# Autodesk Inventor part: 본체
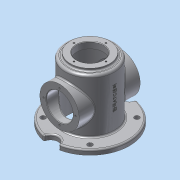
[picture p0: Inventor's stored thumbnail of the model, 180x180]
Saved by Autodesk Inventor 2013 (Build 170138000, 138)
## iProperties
Created: 2018-04
Part Number: 본체
Material: 알루미늄 6061
Document SubType Name: Modeling
Designer: dgall
Density: 2.71 g/cm^3
Mass: 1151.24 g
Surface Area: 1200.37 cm^2
Volume: 424.812 cm^3
Author: dgall
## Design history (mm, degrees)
sketch "스케치1"
  geometry: C1 r 50 at (0, 0); 1 further point
  constraints: 1 centre point, 1 coincident
  dimensions: "d0" = 100 diameter of C1
extrude "돌출1" new body sketch "스케치1" distance "d1" = 110; taper "d2" = 0 deg
fillet "모깎기1" dims "d3" = 5
sketch "스케치2"
  geometry: C1 r 45 at (0, 0) reference; C2 r 50 at (0, 0) reference; C3 r 80 at (0, 0)
  constraints: 1 centre point, 1 coincident
  dimensions: "d5" = 160 diameter of C3
extrude "돌출2" join sketch "스케치2" distance "d6" = 10; taper "d7" = 0 deg
sketch "스케치3"
  geometry: C1 r 45 at (0, 0) reference; C2 r 80 at (0, 0) reference; C3 r 50 at (0, 0)
  constraints: 1 centre point, 1 coincident
  dimensions: "d8" = 100 diameter of C3
extrude "돌출3" join sketch "스케치3" distance "d9" = 8; taper "d10" = 0 deg
sketch "스케치4"
  geometry: C1 r 45 at (0, 0) reference; C2 r 40 at (0, 0)
  constraints: 1 centre point, 1 coincident
  dimensions: "d11" = 80 diameter of C2
extrude "돌출4" join sketch "스케치4" distance "d12" = 5; taper "d13" = 0 deg
hole "구멍1" diameter "d16" = 54; stored, may be unused: countersink angle "d20" = 90 deg, drill point angle "d22" = 0 deg; dims "d17" = 6, "d18" = 4, "d19" = 2, "d21" = 13, "d87" = 10, "d88" = 10
node "작업 평면1"
sketch "스케치5"
  geometry: L1 (-80, -10)-(80, -10) reference; C1 r 40 at (0, 50); 1 further point
  constraints: 1 centre point, 1 vertical alignment
  dimensions: "d24" = 80 diameter of C1; "d25" = 60 distance from line of C1.centre L1
extrude "돌출5" join sketch "스케치5" stored distance "d26" = 5; taper "d27" = 0 deg
sketch "스케치6" dims "d28" = 65
  geometry: L1 (0, 0)-(0, -32.5); C1 r 40 at (0, 0) reference; 2 further points
  constraints: 2 coincident, 2 end point, 1 vertical, 1 vertical alignment, 2 other
hole "구멍2" sketch "스케치6" at (0, -32.5) diameter "d29" = 3.242; stored, may be unused: countersink angle "d33" = 90 deg, drill point angle "d35" = 118 deg; dims "d30" = 8, "d31" = 4, "d32" = 2, "d34" = 10
sketch "스케치7" dims "d48" = 160, "d50" = 135
  geometry: L1 (0, 0)-(0, -80); L2 (0, 0)-(0, -80); L3 (0, 0)-(-47.73, -47.73); C1 r 50 at (0, 0) reference; C2 r 15 at (0, -80); C3 r 5 at (-47.73, -47.73)
  constraints: 6 end point, 4 coincident, 2 centre point, 1 collinear, 1 vertical, 1 vertical alignment, 5 other
  dimensions: "d49" = 30 diameter of C2; "d51" = 45 deg angle of L3 L2; "d52" = 10 diameter of C3
extrude "돌출6" cut sketch "스케치7" distance "d53" = 10; taper "d54" = 0 deg
extrude "돌출7" cut sketch "스케치7" distance "d55" = 10; taper "d56" = 0 deg
sketch "스케치8" dims "d60" = 65
  geometry: L1 (0, 0)-(0, 32.5); C1 r 40 at (0, 0) reference; 1 further point
  constraints: 2 coincident, 2 end point, 1 vertical, 1 vertical alignment, 2 other
hole "구멍4" sketch "스케치8" at (0, 32.5) diameter "d61" = 3.242; stored, may be unused: countersink angle "d65" = 90 deg, drill point angle "d67" = 118 deg; dims "d62" = 8, "d63" = 4, "d64" = 2, "d66" = 10
node "작업 평면4"
sketch "스케치9"
  geometry: L1 (78.594, 0)-(-78.594, 0) reference; L2 (-78.594, -10)-(78.594, -10) reference; 3 further points
  constraints: 1 midpoint, 1 vertical alignment, 1 other
  dimensions: "d72" = 70 distance from line of point (0, 60) L2
feature "엠보싱1" sketch "스케치9" dims "d73" = 0.5, "d74" = 0
chamfer "모따기1" distance "d78" = 1; stored, may be unused: second distance "d79" = 2, angle "d80" = 45 deg
sketch "스케치10"
  geometry: L1 (-28, 115)-(-27, 114) reference; L2 (-27, 114)-(-27, 102) reference; L3 (-30.879, 105)-(-30.879, 115) reference; L4 (-30.879, 115)-(-28, 115) reference; L5 (27, 114)-(28, 115) reference; L6 (28, 115)-(30.879, 115) reference; L7 (30.879, 115)-(30.879, 105) reference; L8 (27, 102)-(27, 114) reference; L9 (-51.026, 17.5)-(-52, 19.121) reference; L10 (-62, 15.879)-(-52, 15.879) reference; L11 (-45, -18)-(-49, -18) reference; L12 (50, -17)-(49, -18) reference; L13 (50, -10)-(50, -17) reference; L14 (-50, -10)-(-65, -10) reference; L15 (-65, -10)-(-65, 0) reference; L16 (-65, 0)-(-50, 0) reference; L17 (-50, 10)-(-62, 10) reference; L18 (-62, 10)-(-62, 15.879) reference; L19 (-52, 19.121)-(-62, 19.121) reference; L20 (-52, 15.879)-(-51.026, 17.5) reference; L21 (-52, 80.879)-(-51.026, 82.5) reference; L22 (-51.026, 82.5)-(-52, 84.121) reference; L23 (-52, 84.121)-(-62, 84.121) reference; L24 (-62, 84.121)-(-62, 90) reference; L25 (-62, 90)-(-50, 90) reference; L26 (-50, 90)-(-50, 105) reference; L27 (-45, 110)-(-40, 110) reference; L28 (-40, 110)-(-40, 115) reference; L29 (-40, 115)-(-34.121, 115) reference; L30 (-34.121, 115)-(-34.121, 105) reference; L31 (-62, 80.879)-(-52, 80.879) reference; L32 (52, 19.121)-(51.026, 17.5) reference; L33 (51.026, 17.5)-(52, 15.879) reference; L34 (52, 15.879)-(62, 15.879) reference; L35 (62, 15.879)-(62, 10) reference; L36 (62, 10)-(50, 10) reference; L37 (50, 0)-(65, 0) reference; L38 (65, 0)-(65, -10) reference; L39 (65, -10)-(50, -10) reference; L40 (-50, -17)-(-50, -10) reference; L41 (-49, -18)-(-50, -17) reference; L42 (49, -18)-(45, -18) reference; L43 (62, 19.121)-(52, 19.121) reference; L44 (51.026, 82.5)-(52, 80.879) reference; L45 (52, 80.879)-(62, 80.879) reference; L46 (62, 80.879)-(62, 19.121) reference; L47 (34.121, 105)-(34.121, 115) reference; L48 (34.121, 115)-(40, 115) reference; L49 (40, 115)-(40, 110) reference; L50 (40, 110)-(45, 110) reference; L51 (50, 105)-(50, 90) reference; L52 (50, 90)-(62, 90) reference; L53 (62, 90)-(62, 84.121) reference; L54 (62, 84.121)-(52, 84.121) reference; L55 (52, 84.121)-(51.026, 82.5) reference; L56 (45, -18)-(45, 0) reference; L57 (45, 0)-(-45, 0) reference; L58 (-45, 0)-(-45, -18) reference; L59 (-62, 19.121)-(-62, 80.879) reference; L60 (-34.121, 105)-(-32.5, 104.026) reference; L61 (-32.5, 104.026)-(-30.879, 105) reference; L62 (-27, 102)-(27, 102) reference; L63 (30.879, 105)-(32.5, 104.026) reference; L64 (32.5, 104.026)-(34.121, 105) reference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; A1 r 5 centre (-45, 105) between (-45, 110) and (-50, 105) reference; A2 r 5 centre (45, 105) between (50, 105) and (45, 110) reference; 1 further point
  node "절단 모서리 투영1"
sketch "스케치11"
  geometry: C1 r 45 at (0, 0) reference; C2 r 49 at (0, 0) reference; C3 r 45 at (0, 0)
  constraints: 1 centre point, 1 coincident
  dimensions: "d83" = 90 diameter of C3
extrude "돌출8" cut sketch "스케치11" distance "d85" = 120; taper "d86" = 0 deg
hole "구멍5" diameter "d91" = 54; stored, may be unused: countersink angle "d95" = 90 deg, drill point angle "d97" = 118 deg; dims "d89" = 10, "d90" = 10, "d92" = 8, "d93" = 4, "d94" = 2, "d96" = 10
hole "구멍6" diameter "d100" = 54; stored, may be unused: countersink angle "d104" = 90 deg, drill point angle "d106" = 118 deg; dims "d98" = 10, "d99" = 10, "d101" = 8, "d102" = 4, "d103" = 2, "d105" = 10
chamfer "모따기2" distance "d108" = 1; stored, may be unused: second distance "d109" = 2, angle "d110" = 45 deg
sketch "스케치12"
  geometry: L1 (-51.026, 17.5)-(-52, 19.121) reference; L2 (-52, 19.121)-(-62, 19.121) reference; L3 (-62, 19.121)-(-62, 22) reference; L4 (-62, 22)-(-61, 23) reference; L5 (-61, 23)-(-45, 23) reference; L6 (-45, 23)-(-45, -18) reference; L7 (-45, -18)-(-49, -18) reference; L8 (-49, -18)-(-50, -17) reference; L9 (-50, -17)-(-50, -10) reference; L10 (-50, -10)-(-65, -10) reference; L11 (-65, -10)-(-65, 0) reference; L12 (-65, 0)-(-50, 0) reference; L13 (-50, 10)-(-62, 10) reference; L14 (-62, 10)-(-62, 15.879) reference; L15 (-62, 15.879)-(-52, 15.879) reference; L16 (-52, 15.879)-(-51.026, 17.5) reference; L17 (-52, 80.879)-(-51.026, 82.5) reference; L18 (-51.026, 82.5)-(-52, 84.121) reference; L19 (-52, 84.121)-(-62, 84.121) reference; L20 (-62, 84.121)-(-62, 90) reference; L21 (-62, 90)-(-50, 90) reference; L22 (-50, 90)-(-50, 105) reference; L23 (-45, 110)-(-40, 110) reference; L24 (-40, 110)-(-40, 115) reference; L25 (-40, 115)-(-34.121, 115) reference; L26 (-34.121, 115)-(-34.121, 105) reference; L27 (-34.121, 105)-(-32.5, 104.026) reference; L28 (-32.5, 104.026)-(-30.879, 105) reference; L29 (-30.879, 105)-(-30.879, 115) reference; L30 (-30.879, 115)-(-28, 115) reference; L31 (-28, 115)-(-27, 114) reference; L32 (-27, 114)-(-27, 102) reference; L33 (-27, 102)-(-45, 102) reference; L34 (-45, 77)-(-61, 77) reference; L35 (-61, 77)-(-62, 78) reference; L36 (-62, 78)-(-62, 80.879) reference; L37 (-62, 80.879)-(-52, 80.879) reference; L38 (52, 19.121)-(51.026, 17.5) reference; L39 (51.026, 17.5)-(52, 15.879) reference; L40 (52, 15.879)-(62, 15.879) reference; L41 (62, 15.879)-(62, 10) reference; L42 (62, 10)-(50, 10) reference; L43 (50, 0)-(65, 0) reference; L44 (65, 0)-(65, -10) reference; L45 (65, -10)-(50, -10) reference; L46 (50, -10)-(50, -17) reference; L47 (50, -17)-(49, -18) reference; L48 (49, -18)-(45, -18) reference; L49 (45, -18)-(45, 23) reference; L50 (45, 23)-(61, 23) reference; L51 (61, 23)-(62, 22) reference; L52 (62, 22)-(62, 19.121) reference; L53 (62, 19.121)-(52, 19.121) reference; L54 (51.026, 82.5)-(52, 80.879) reference; L55 (52, 80.879)-(62, 80.879) reference; L56 (62, 80.879)-(62, 78) reference; L57 (62, 78)-(61, 77) reference; L58 (61, 77)-(45, 77) reference; L59 (45, 102)-(27, 102) reference; L60 (27, 102)-(27, 114) reference; L61 (27, 114)-(28, 115) reference; L62 (28, 115)-(30.879, 115) reference; L63 (30.879, 115)-(30.879, 105) reference; L64 (30.879, 105)-(32.5, 104.026) reference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; A1 r 5 centre (-45, 105) between (-45, 110) and (-50, 105) reference; A2 r 5 centre (45, 105) between (50, 105) and (45, 110) reference; 1 further point
  node "절단 모서리 투영2"
fillet "모깎기6" dims "d111" = 3
fillet "모깎기7" dims "d112" = 3
fillet "모깎기8" dims "d113" = 3
node "솔리드1"
pattern_circular "원형 패턴1" dims angle "d37" = 360 deg
mirror "대칭1"
pattern_circular "원형 패턴2" dims angle "d58" = 360 deg
mirror "대칭2"
pattern_circular "원형 패턴3" dims angle "d69" = 360 deg
node "작업 평면2"
node "작업 평면3"
other parameters: "d23" = 62
